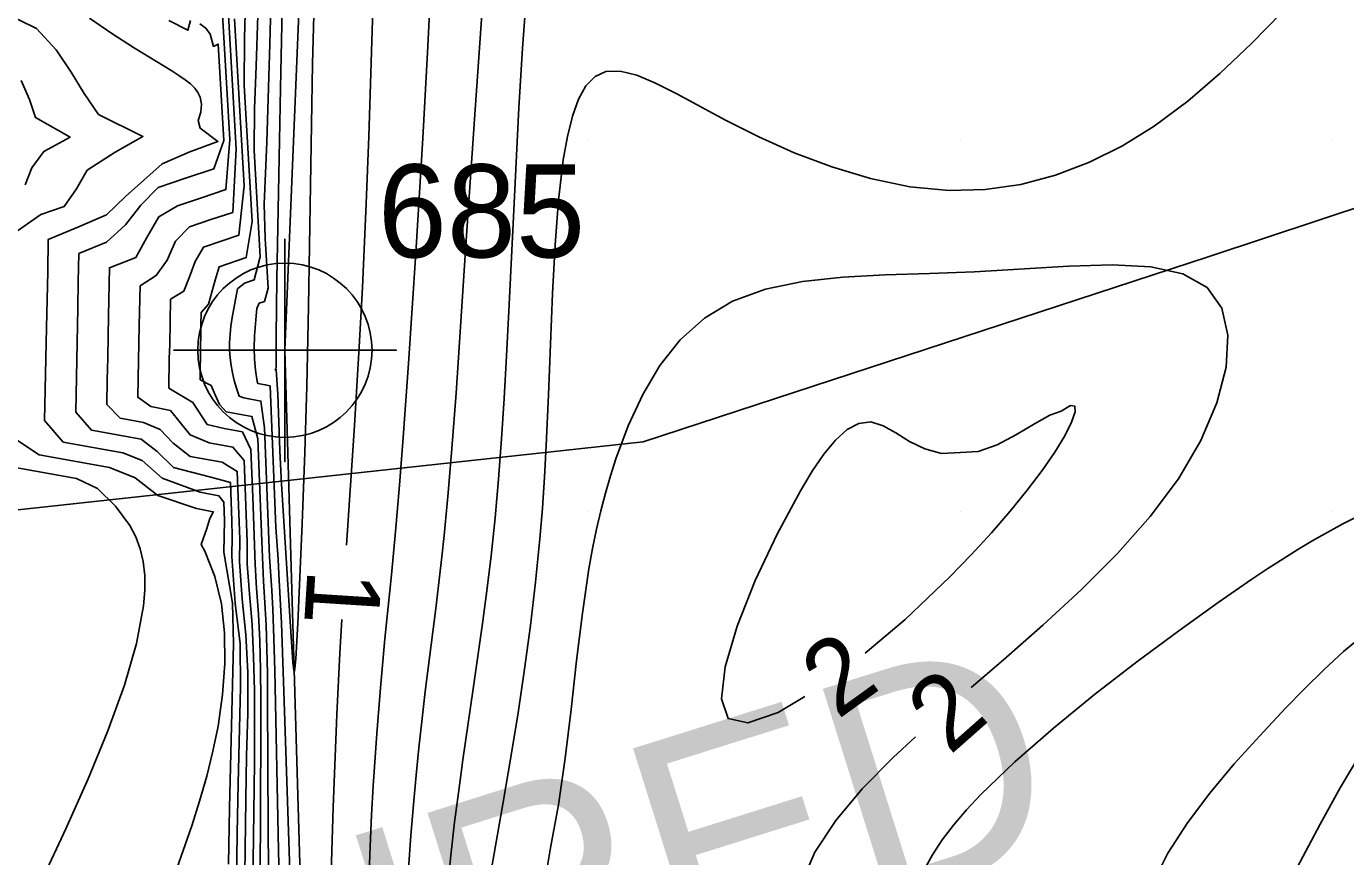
# Model space of a CAD drawing. Extents: x 2602990 to 2605851, y 618069 to 619180.
# Drawn here: x 2603644.86 to 2603680.36, y 618430.72 to 618453.06 of the extents above; entities that cross this region are included whole.
import ezdxf

# ---------------------------------------------------------------- set-up
doc = ezdxf.new("R2010")
doc.units = 0
for name, color, linetype in [('DTM Contours Major', 7, 'Continuous'), ('DTM Contours Minor', 7, 'Continuous'), ('DTM Contours Minor Text', 7, 'Continuous'), ('Exist DTM Breakline', 7, 'Continuous'), ('Exist DTM Breakline Cogo Number', 7, 'Continuous'), ('Exist DTM Breakline Cogo Point CELL', 7, 'Continuous'), ('Exist DTM Crownline', 7, 'Continuous'), ('Exist DTM QL2 LIDAR Elevation Point', 7, 'Continuous'), ('Exist Roads EOP', 7, 'Continuous'), ('PH Exist DTM Obscure Area', 7, 'Continuous'), ('PH Exist DTM Obscure Area Text', 7, 'Continuous')]:
    doc.layers.add(name, color=color, linetype=linetype)

# ---------------------------------------------------------------- blocks, each defined once
blk = doc.blocks.new('EXIST DTM BREAKLINE COGO POINT')
at = {"layer": 'Exist DTM Breakline Cogo Point CELL'}
blk.add_lwpolyline([(0, 0.06), (0, -0.06), (0, 0), (0.06, 0), (-0.06, 0)], dxfattribs=at)
blk.add_circle((0, 0), 0.04688, dxfattribs=at)

msp = doc.modelspace()

# ---------------------------------------------------------------- linework, layer by layer
at = {"layer": 'DTM Contours Major'}
for points in [[(2603650.289, 618453.519), (2603650.508, 618449.758), (2603650.417, 618448.058), (2603649.831, 618447.866), (2603649.254, 618447.667), (2603648.872, 618447.284), (2603648.649, 618446.772), (2603648.358, 618446.355), (2603647.922, 618446.081), (2603647.9, 618445.01), (2603647.888, 618444.542), (2603647.884, 618444.084), (2603647.861, 618443.081), (2603648.209, 618442.83), (2603648.741, 618442.727), (2603648.998, 618442.402), (2603649.268, 618442.07), (2603649.779, 618441.857), (2603650.42, 618441.743), (2603650.72, 618441.381), (2603650.806, 618439.196), (2603650.808, 618438.597), (2603650.866, 618437.79), (2603650.936, 618436.97), (2603650.979, 618436.102), (2603651, 618435.19), (2603651.006, 618434.237), (2603651.001, 618433.249), (2603650.941, 618428.604)], [(2603657.335, 618430.137), (2603657.693, 618432.184), (2603657.899, 618433.395), (2603658.092, 618434.587), (2603658.269, 618435.766), (2603658.428, 618436.937), (2603658.566, 618438.105), (2603658.681, 618439.275), (2603658.747, 618440.1), (2603658.803, 618440.936), (2603658.849, 618441.787), (2603658.909, 618443.145), (2603659.018, 618445.879), (2603659.088, 618447.181), (2603659.182, 618448.39), (2603659.31, 618449.47), (2603659.419, 618450.099), (2603659.553, 618450.646), (2603659.718, 618451.103), (2603659.92, 618451.461), (2603660.164, 618451.712), (2603660.455, 618451.849), (2603660.837, 618451.862), (2603661.284, 618451.75), (2603661.792, 618451.536), (2603662.361, 618451.246), (2603663.673, 618450.535), (2603664.566, 618450.088), (2603665.524, 618449.661), (2603666.531, 618449.28), (2603667.573, 618448.968), (2603668.632, 618448.748), (2603669.694, 618448.646), (2603670.663, 618448.672), (2603671.617, 618448.812), (2603672.552, 618449.058), (2603673.465, 618449.406), (2603674.352, 618449.848), (2603675.21, 618450.379), (2603676.108, 618451.048), (2603676.973, 618451.793), (2603677.812, 618452.592), (2603678.633, 618453.425)], [(2603680.746, 618439.909), (2603680.283, 618439.676), (2603679.795, 618439.411), (2603679.472, 618439.226), (2603679.076, 618438.989), (2603678.674, 618438.738), (2603678.261, 618438.471), (2603677.835, 618438.186), (2603677.392, 618437.883), (2603676.929, 618437.56), (2603675.867, 618436.8), (2603674.744, 618435.967), (2603673.605, 618435.085), (2603672.495, 618434.179), (2603671.46, 618433.272), (2603670.546, 618432.39), (2603670.158, 618431.976), (2603669.81, 618431.57), (2603669.503, 618431.169), (2603669.24, 618430.77), (2603669.02, 618430.368)]]:
    msp.add_lwpolyline(points, dxfattribs=at)
at = {"layer": 'DTM Contours Minor'}
for points in [[(2603652.67, 618455.99), (2603652.563, 618452.052), (2603652.458, 618445.524), (2603652.411, 618443.383), (2603652.357, 618441.593), (2603652.285, 618439.69), (2603652.163, 618437.007), (2603652.112, 618436.047), (2603652.09, 618435.781), (2603652.08, 618435.714), (2603652.069, 618435.697), (2603652.057, 618435.734), (2603652.033, 618435.954), (2603651.96, 618437.047), (2603651.729, 618440.742), (2603651.686, 618441.646), (2603651.625, 618443.17), (2603651.586, 618443.825), (2603651.553, 618443.831), (2603651.586, 618443.868), (2603651.581, 618444.726), (2603651.6, 618446.264), (2603651.7, 618451.399), (2603651.784, 618455.247)], [(2603651.993, 618428.981), (2603651.784, 618435.433), (2603651.724, 618437.006), (2603651.659, 618438.325), (2603651.634, 618438.73), (2603651.573, 618439.582), (2603651.422, 618443.388), (2603651.29, 618443.42), (2603651.091, 618443.455), (2603651.071, 618443.508), (2603651.025, 618443.81), (2603650.998, 618444.11), (2603650.989, 618444.413), (2603650.999, 618444.735), (2603651.044, 618445.27), (2603651.064, 618445.473), (2603651.131, 618445.615), (2603651.273, 618445.663), (2603651.366, 618446.016), (2603651.288, 618447.354), (2603651.259, 618448.283), (2603651.33, 618449.944), (2603651.416, 618452.59), (2603651.498, 618455.661)], [(2603655.815, 618455.587), (2603655.658, 618452.362), (2603655.531, 618450.056), (2603655.342, 618446.973), (2603655.146, 618443.991), (2603655.005, 618441.998), (2603654.906, 618440.72), (2603654.797, 618439.467), (2603654.684, 618438.301), (2603654.51, 618436.579), (2603654.388, 618435.267), (2603654.29, 618434.035), (2603654.196, 618432.625), (2603654.152, 618431.84), (2603654.11, 618430.996), (2603653.988, 618427.677)], [(2603650.048, 618454.907), (2603650.334, 618450.015), (2603650.234, 618448.671), (2603649.574, 618448.447), (2603648.931, 618448.234), (2603648.424, 618447.94), (2603648.108, 618447.383), (2603647.81, 618446.847), (2603647.1, 618446.57), (2603647.072, 618445.286), (2603647.054, 618444.15), (2603647.037, 618443.544), (2603647.029, 618442.891), (2603647.39, 618442.516), (2603648.011, 618442.404), (2603648.462, 618442.215), (2603648.816, 618441.844), (2603649.272, 618441.491), (2603650.135, 618441.338), (2603650.537, 618441.086), (2603650.609, 618439.263), (2603650.598, 618438.665), (2603650.672, 618437.653), (2603650.766, 618436.701), (2603650.82, 618435.679), (2603650.818, 618434.578), (2603650.789, 618433.428), (2603650.768, 618432.262), (2603650.699, 618426.93)], [(2603657.21, 618454.674), (2603656.927, 618450.696), (2603656.681, 618447.043), (2603656.424, 618443.196), (2603656.314, 618441.708), (2603656.214, 618440.514), (2603656.103, 618439.362), (2603656.042, 618438.791), (2603655.876, 618437.401), (2603655.597, 618435.169), (2603655.501, 618434.357), (2603655.423, 618433.653), (2603655.347, 618432.912), (2603655.275, 618432.125), (2603655.207, 618431.287), (2603655.144, 618430.391)], [(2603651.386, 618429.328), (2603651.37, 618431.471), (2603651.355, 618434.959), (2603651.347, 618435.653), (2603651.333, 618436.315), (2603651.312, 618436.947), (2603651.283, 618437.553), (2603651.243, 618438.136), (2603651.197, 618439.207), (2603651.087, 618441.968), (2603650.93, 618442.568), (2603650.236, 618442.692), (2603650.061, 618442.887), (2603649.942, 618443.145), (2603649.835, 618443.398), (2603649.537, 618443.555), (2603649.536, 618443.864), (2603649.548, 618444.158), (2603649.561, 618445.032), (2603649.57, 618445.361), (2603649.767, 618445.585), (2603649.947, 618446.235), (2603650.047, 618446.595), (2603650.779, 618446.84), (2603650.941, 618447.81), (2603650.728, 618451.476), (2603650.732, 618452.742), (2603650.772, 618454.07)], [(2603651.732, 618427.542), (2603651.645, 618430.89), (2603651.547, 618435.73), (2603651.513, 618436.859), (2603651.492, 618437.381), (2603651.467, 618437.88), (2603651.409, 618438.786), (2603651.271, 618442.258), (2603651.176, 618442.981), (2603650.717, 618443.064), (2603650.585, 618443.116), (2603650.518, 618443.329), (2603650.459, 618443.535), (2603650.41, 618443.736), (2603650.371, 618443.94), (2603650.346, 618444.143), (2603650.333, 618444.349), (2603650.333, 618444.559), (2603650.344, 618444.774), (2603650.368, 618444.998), (2603650.403, 618445.226), (2603650.548, 618445.999), (2603650.732, 618446.152), (2603650.993, 618446.239), (2603651.157, 618446.866), (2603650.99, 618449.722), (2603651.002, 618450.854), (2603651.048, 618451.992), (2603651.115, 618454.188)], [(2603658.328, 618454.039), (2603658.212, 618452.477), (2603658.116, 618450.874), (2603657.968, 618447.94), (2603657.845, 618445.397), (2603657.783, 618444.196), (2603657.718, 618443.05), (2603657.649, 618441.962), (2603657.567, 618440.876), (2603657.475, 618439.836), (2603657.368, 618438.819), (2603657.262, 618437.941), (2603657.145, 618437.056), (2603656.886, 618435.239), (2603656.61, 618433.326), (2603656.497, 618432.501), (2603656.386, 618431.645), (2603656.28, 618430.751), (2603656.182, 618429.812)], [(2603654.191, 618453.814), (2603654.074, 618450.1), (2603654.007, 618448.295), (2603653.907, 618446.037), (2603653.821, 618444.44), (2603653.69, 618442.32), (2603653.476, 618439.102)], [(2603644.182, 618453.475), (2603645.138, 618453.008), (2603645.666, 618452.432), (2603646.071, 618451.829), (2603646.422, 618451.255), (2603646.809, 618450.69), (2603648.001, 618450.096), (2603647.256, 618449.68), (2603646.497, 618449.192), (2603646.211, 618448.691), (2603645.883, 618448.212), (2603645.257, 618448.002), (2603644.622, 618447.558)], [(2603646.564, 618453.287), (2603647.161, 618452.873), (2603647.744, 618452.492), (2603648.778, 618451.867), (2603648.968, 618451.745), (2603649.135, 618451.629), (2603649.276, 618451.515), (2603649.392, 618451.401), (2603649.48, 618451.284), (2603649.541, 618451.16), (2603649.579, 618450.967), (2603649.559, 618450.756), (2603649.483, 618450.529), (2603649.542, 618450.322), (2603650.016, 618449.968), (2603649.26, 618449.687), (2603648.52, 618449.36), (2603647.529, 618448.481), (2603647.02, 618447.996), (2603646.252, 618447.66), (2603645.45, 618447.328), (2603645.438, 618446.46), (2603645.403, 618444.963), (2603645.356, 618442.455), (2603645.855, 618441.876), (2603647.458, 618441.589), (2603647.975, 618441.379), (2603648.521, 618440.909), (2603649.538, 618440.528), (2603650.046, 618440.434), (2603650.179, 618440.259), (2603650.198, 618439.766), (2603650.18, 618438.915), (2603650.413, 618437.54), (2603650.438, 618436.448), (2603650.332, 618432.034), (2603650.302, 618430.522)], [(2603651.156, 618430.065), (2603651.174, 618434.12), (2603651.172, 618434.953), (2603651.162, 618435.752), (2603651.141, 618436.517), (2603651.106, 618437.248), (2603651.053, 618437.946), (2603651.021, 618438.582), (2603650.955, 618440.406), (2603650.904, 618441.677), (2603650.678, 618442.155), (2603650.185, 618442.245), (2603649.724, 618442.346), (2603649.347, 618442.946), (2603648.696, 618443.329), (2603648.71, 618444.129), (2603648.722, 618444.5), (2603648.743, 618445.722), (2603649.103, 618445.938), (2603649.253, 618446.322), (2603649.407, 618446.74), (2603649.632, 618447.124), (2603650.584, 618447.448), (2603650.726, 618448.77), (2603650.464, 618453.267)], [(2603648.699, 618453.217), (2603649.209, 618452.958), (2603649.281, 618453.22)], [(2603649.535, 618453.131), (2603649.691, 618453.015), (2603649.807, 618452.853), (2603649.902, 618452.526), (2603650.025, 618452.585), (2603650.176, 618449.989), (2603649.908, 618449.232), (2603649.148, 618448.98), (2603648.413, 618448.727), (2603647.941, 618448.252), (2603647.533, 618447.72), (2603647.024, 618447.253), (2603646.279, 618446.948), (2603646.259, 618446.185), (2603646.25, 618445.489), (2603646.192, 618442.68), (2603646.614, 618442.198), (2603647.95, 618441.958), (2603648.382, 618441.62), (2603648.823, 618441.192), (2603649.829, 618440.933), (2603650.353, 618440.785), (2603650.394, 618439.755), (2603650.402, 618439.349), (2603650.388, 618438.801), (2603650.485, 618437.538), (2603650.617, 618436.451), (2603650.623, 618435.285), (2603650.561, 618432.687), (2603650.534, 618431.35), (2603650.435, 618423.821)], [(2603644.727, 618451.604), (2603644.95, 618451.095), (2603645.108, 618450.607), (2603646.041, 618450.085), (2603645.33, 618449.7), (2603645.01, 618449.254), (2603644.836, 618448.799)], [(2603658.969, 618430.954), (2603659.182, 618432.117), (2603659.361, 618433.373), (2603659.518, 618434.681), (2603659.668, 618435.995), (2603659.824, 618437.272), (2603660, 618438.469), (2603660.098, 618439.013), (2603660.204, 618439.531), (2603660.319, 618440.027), (2603660.444, 618440.505), (2603660.58, 618440.97), (2603660.726, 618441.424), (2603661.057, 618442.313), (2603661.447, 618443.157), (2603661.909, 618443.935), (2603662.457, 618444.627), (2603663.104, 618445.213), (2603663.864, 618445.671), (2603664.752, 618445.993), (2603665.747, 618446.197), (2603666.827, 618446.313), (2603667.972, 618446.374), (2603669.16, 618446.411), (2603670.37, 618446.456), (2603672.912, 618446.612), (2603674.077, 618446.645), (2603675.114, 618446.59), (2603675.979, 618446.401), (2603676.63, 618446.034), (2603677.025, 618445.478), (2603677.192, 618444.75), (2603677.144, 618443.889), (2603676.896, 618442.933), (2603676.463, 618441.92), (2603675.859, 618440.89), (2603675.1, 618439.872), (2603674.217, 618438.875), (2603673.242, 618437.9), (2603672.21, 618436.947), (2603671.153, 618436.018), (2603670.287, 618435.27)], [(2603667.43, 618436.193), (2603668.504, 618437.104), (2603669.707, 618438.246), (2603670.284, 618438.842), (2603670.83, 618439.436), (2603671.335, 618440.019), (2603671.792, 618440.582), (2603672.194, 618441.114), (2603672.533, 618441.607), (2603672.8, 618442.047), (2603672.986, 618442.416), (2603673.08, 618442.689), (2603673.072, 618442.843), (2603672.951, 618442.857), (2603672.705, 618442.705), (2603672.397, 618442.6), (2603671.983, 618442.367), (2603671.5, 618442.079), (2603670.983, 618441.806), (2603670.471, 618441.621), (2603670, 618441.595)], [(2603670, 618441.595), (2603669.489, 618441.572), (2603669.035, 618441.691), (2603668.627, 618441.894), (2603668.257, 618442.122), (2603667.912, 618442.316), (2603667.583, 618442.417), (2603667.264, 618442.381), (2603666.948, 618442.213), (2603666.634, 618441.93), (2603666.321, 618441.55), (2603666.007, 618441.091), (2603665.691, 618440.568), (2603665.059, 618439.399), (2603664.47, 618438.15), (2603663.985, 618436.927), (2603663.663, 618435.831), (2603663.563, 618434.966), (2603663.745, 618434.436), (2603664.272, 618434.319), (2603665.088, 618434.601), (2603665.809, 618435.026)], [(2603644.515, 618441.995), (2603645.205, 618441.535), (2603647.099, 618441.192), (2603647.789, 618440.916), (2603648.404, 618440.443), (2603649.441, 618440.087), (2603649.893, 618440.003), (2603649.791, 618439.796), (2603649.715, 618439.548), (2603649.565, 618439.118), (2603649.662, 618438.939), (2603649.934, 618438.262), (2603650.11, 618437.524), (2603650.198, 618436.739), (2603650.206, 618435.919), (2603650.144, 618435.08), (2603650.021, 618434.234), (2603649.884, 618433.558), (2603649.718, 618432.886), (2603649.526, 618432.217), (2603649.314, 618431.551), (2603649.086, 618430.887), (2603648.846, 618430.223)], [(2603644.361, 618441.227), (2603646.211, 618440.895), (2603646.778, 618440.628), (2603647.262, 618440.148), (2603647.65, 618439.635), (2603647.81, 618439.33), (2603647.929, 618439.005), (2603648.008, 618438.659), (2603648.049, 618438.289), (2603648.052, 618437.894), (2603648.019, 618437.472), (2603647.83, 618436.46), (2603647.501, 618435.332), (2603647.056, 618434.11), (2603646.523, 618432.817), (2603645.927, 618431.473), (2603645.293, 618430.103), (2603644.612, 618428.656)], [(2603653.349, 618437.106), (2603653.296, 618436.2), (2603653.215, 618434.55), (2603653.141, 618432.725), (2603653.118, 618432.049), (2603653.03, 618429.08)], [(2603681.423, 618437.164), (2603680.301, 618436.238), (2603679.769, 618435.75), (2603679.254, 618435.24), (2603678.743, 618434.714), (2603678.045, 618433.975), (2603677.357, 618433.214), (2603676.702, 618432.433), (2603676.102, 618431.632), (2603675.577, 618430.812), (2603675.15, 618429.975)], [(2603668.788, 618433.946), (2603668.182, 618433.388), (2603667.35, 618432.541), (2603666.64, 618431.693), (2603666.08, 618430.837), (2603665.698, 618429.963)], [(2603680.763, 618433.502), (2603680.208, 618432.571), (2603679.672, 618431.592), (2603679.133, 618430.579), (2603678.52, 618429.438), (2603677.898, 618428.265), (2603677.289, 618427.054), (2603676.712, 618425.795), (2603676.188, 618424.482), (2603675.736, 618423.105), (2603675.44, 618421.968), (2603675.186, 618420.783), (2603674.959, 618419.547), (2603674.521, 618416.911), (2603674.368, 618415.63), (2603673.872, 618413.351), (2603673.46, 618411.223), (2603673.115, 618409.285), (2603672.912, 618407.7), (2603672.924, 618406.631), (2603673.224, 618406.241), (2603674.08, 618406.865), (2603675.783, 618409.536), (2603682.8, 618420.627)], [(2603658.785, 618429.885), (2603658.969, 618430.954)]]:
    msp.add_lwpolyline(points, dxfattribs=at)
at = {"layer": 'Exist DTM Breakline'}
for p, q in [((2603651.819, 618444.348), (2603653.037, 618473.66)), ((2603652.885, 618407.397), (2603651.819, 618444.348))]:
    msp.add_line(p, q, dxfattribs=at)
msp.add_spline([(2603620.929, 618446.882), (2603612.359, 618415.215), (2603610.953, 618372.558), (2603618.76, 618335.828), (2603633.155, 618328.185), (2603650.641, 618336.311)], degree=3, dxfattribs=at)
at = {"layer": 'Exist DTM Crownline'}
msp.add_spline([(2603233.488, 618380.754), (2603285.185, 618400.095), (2603335.457, 618418.629), (2603390.812, 618439.069), (2603440.087, 618457.325), (2603493.996, 618477.231), (2603542.655, 618495.301), (2603600.808, 618516.867), (2603653.659, 618536.362), (2603706.222, 618555.742), (2603764.811, 618577.593), (2603823.52, 618599.847), (2603878.564, 618620.56), (2603937.951, 618643.078), (2603997.369, 618665.789), (2604036.209, 618680.665), (2604055.311, 618688.017)], degree=3, dxfattribs=at)
at = {"layer": 'Exist DTM QL2 LIDAR Elevation Point'}
for p, q in [((2603650, 618450), (2603650, 618450)), ((2603660, 618450), (2603660, 618450)), ((2603670, 618450), (2603670, 618450)), ((2603680, 618450), (2603680, 618450)), ((2603650, 618440), (2603650, 618440)), ((2603660, 618440), (2603660, 618440)), ((2603670, 618440), (2603670, 618440)), ((2603680, 618440), (2603680, 618440))]:
    msp.add_line(p, q, dxfattribs=at)
at = {"layer": 'Exist Roads EOP'}
for points in [[(2603230.17, 618389.98), (2603282.929, 618409.597), (2603332.773, 618427.868), (2603388.167, 618448.413), (2603437.203, 618466.721), (2603490.778, 618486.527), (2603539.039, 618504.558), (2603597.451, 618526.156), (2603651.053, 618545.972), (2603705.208, 618566.084), (2603762.02, 618587.183), (2603820.334, 618609.162), (2603876.341, 618629.99), (2603934.909, 618652.28), (2603996.409, 618675.568), (2604033.216, 618689.957), (2604052.01, 618697.199)], [(2604034.633, 618668.486), (2603984.89, 618650.123), (2603936.767, 618631.654), (2603888.195, 618613.335), (2603837.766, 618594.258), (2603782.918, 618573.705), (2603731.939, 618554.39), (2603671.126, 618532.171), (2603621.822, 618514.106), (2603561.545, 618491.877), (2603506.421, 618471.293), (2603452.163, 618451.33), (2603398.364, 618431.316), (2603341.431, 618410.355), (2603281.65, 618388.199), (2603223.033, 618366.475), (2603185.717, 618352.612)]]:
    msp.add_spline(points, degree=3, dxfattribs=at)
at = {"layer": 'PH Exist DTM Obscure Area'}
msp.add_lwpolyline([(2603620.673, 618420.489), (2603628.196, 618430.92), (2603632.498, 618435.084), (2603644.551, 618440.041), (2603661.459, 618441.879), (2603676.685, 618446.873), (2603689.92, 618451.256), (2603703.212, 618450.584), (2603689.618, 618436.439), (2603677.658, 618423.371), (2603671.253, 618418.008), (2603656.951, 618414.436), (2603642.952, 618415.217), (2603633.838, 618410.293), (2603630.207, 618398.848), (2603629.291, 618386.376), (2603630.839, 618374.285), (2603630.441, 618367.932)], dxfattribs=at)

# ---------------------------------------------------------------- block references
at = {"layer": 'Exist DTM Breakline Cogo Point CELL', "xscale": 50, "yscale": 50}
msp.add_blockref('EXIST DTM BREAKLINE COGO POINT', (2603651.819, 618444.348), dxfattribs=at)

# ---------------------------------------------------------------- texts
at = {"layer": 'DTM Contours Minor Text'}
for s, rotation, p in [('1', 266.3448, (2603652.432, 618438.482)), ('2', 35.7408, (2603666.687, 618434.396)), ('2', 41.4542, (2603669.705, 618433.431))]:
    msp.add_text(s, height=2, rotation=rotation, dxfattribs=at).set_placement(p)
at = {"layer": 'Exist DTM Breakline Cogo Number'}
msp.add_text('685', height=2.5, dxfattribs=at).set_placement((2603654.319, 618446.848))
at = {"layer": 'PH Exist DTM Obscure Area Text'}
msp.add_text('OBSCURED', height=6, rotation=17.4224, dxfattribs=at).set_placement((2603629.603, 618417.434))

doc.saveas('drawing.dxf')
